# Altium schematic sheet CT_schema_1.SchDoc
size 617 x 451 mm
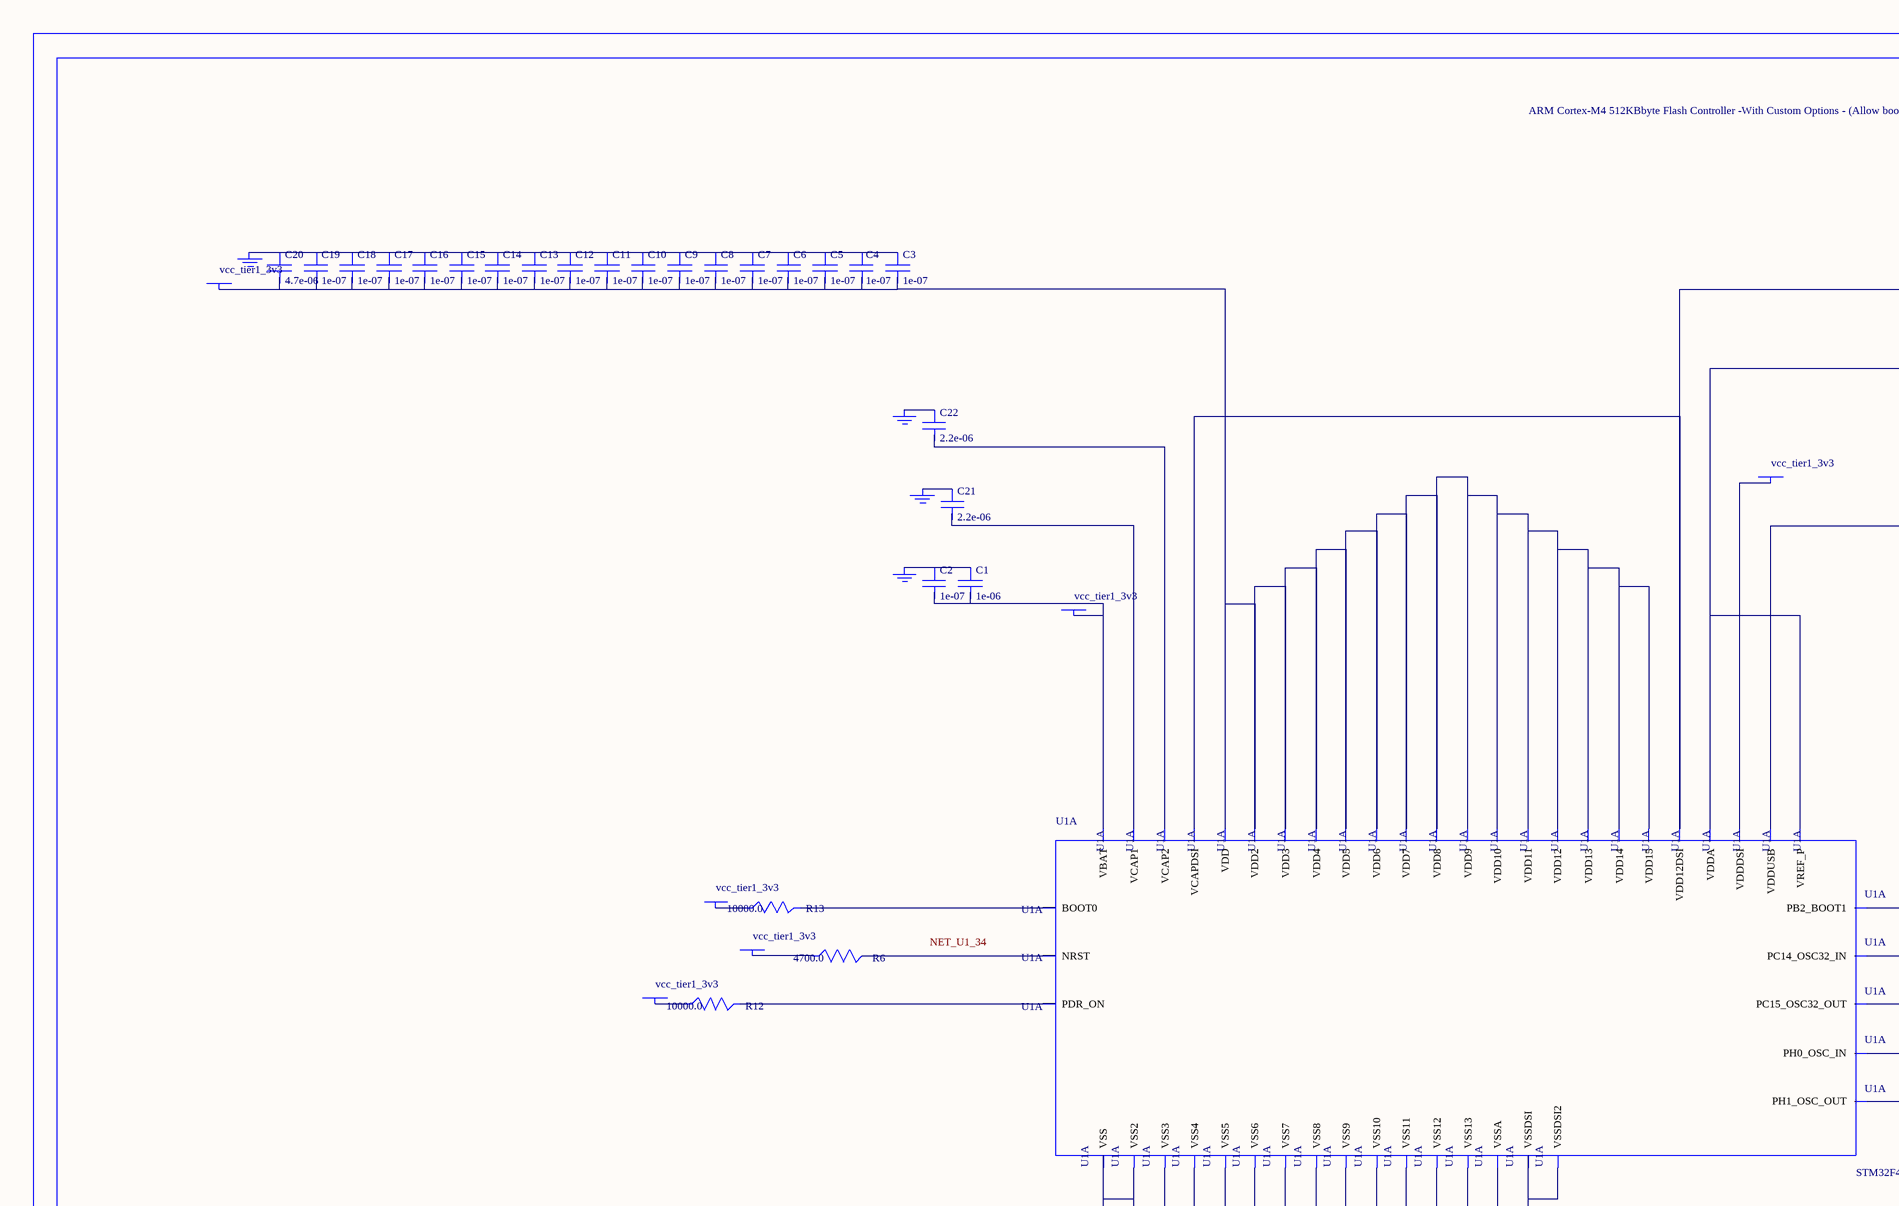
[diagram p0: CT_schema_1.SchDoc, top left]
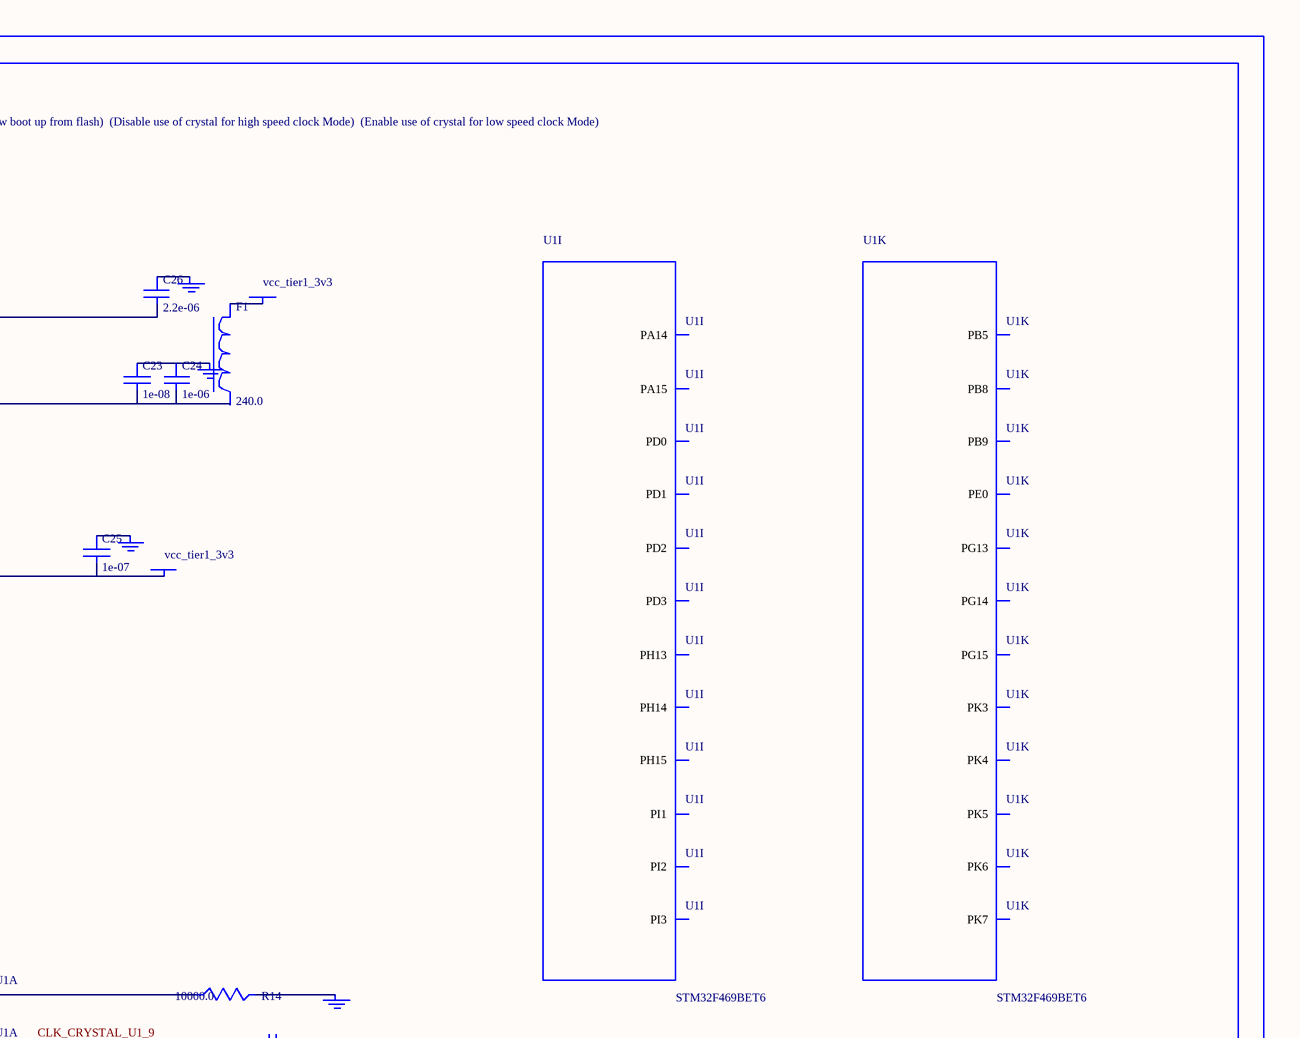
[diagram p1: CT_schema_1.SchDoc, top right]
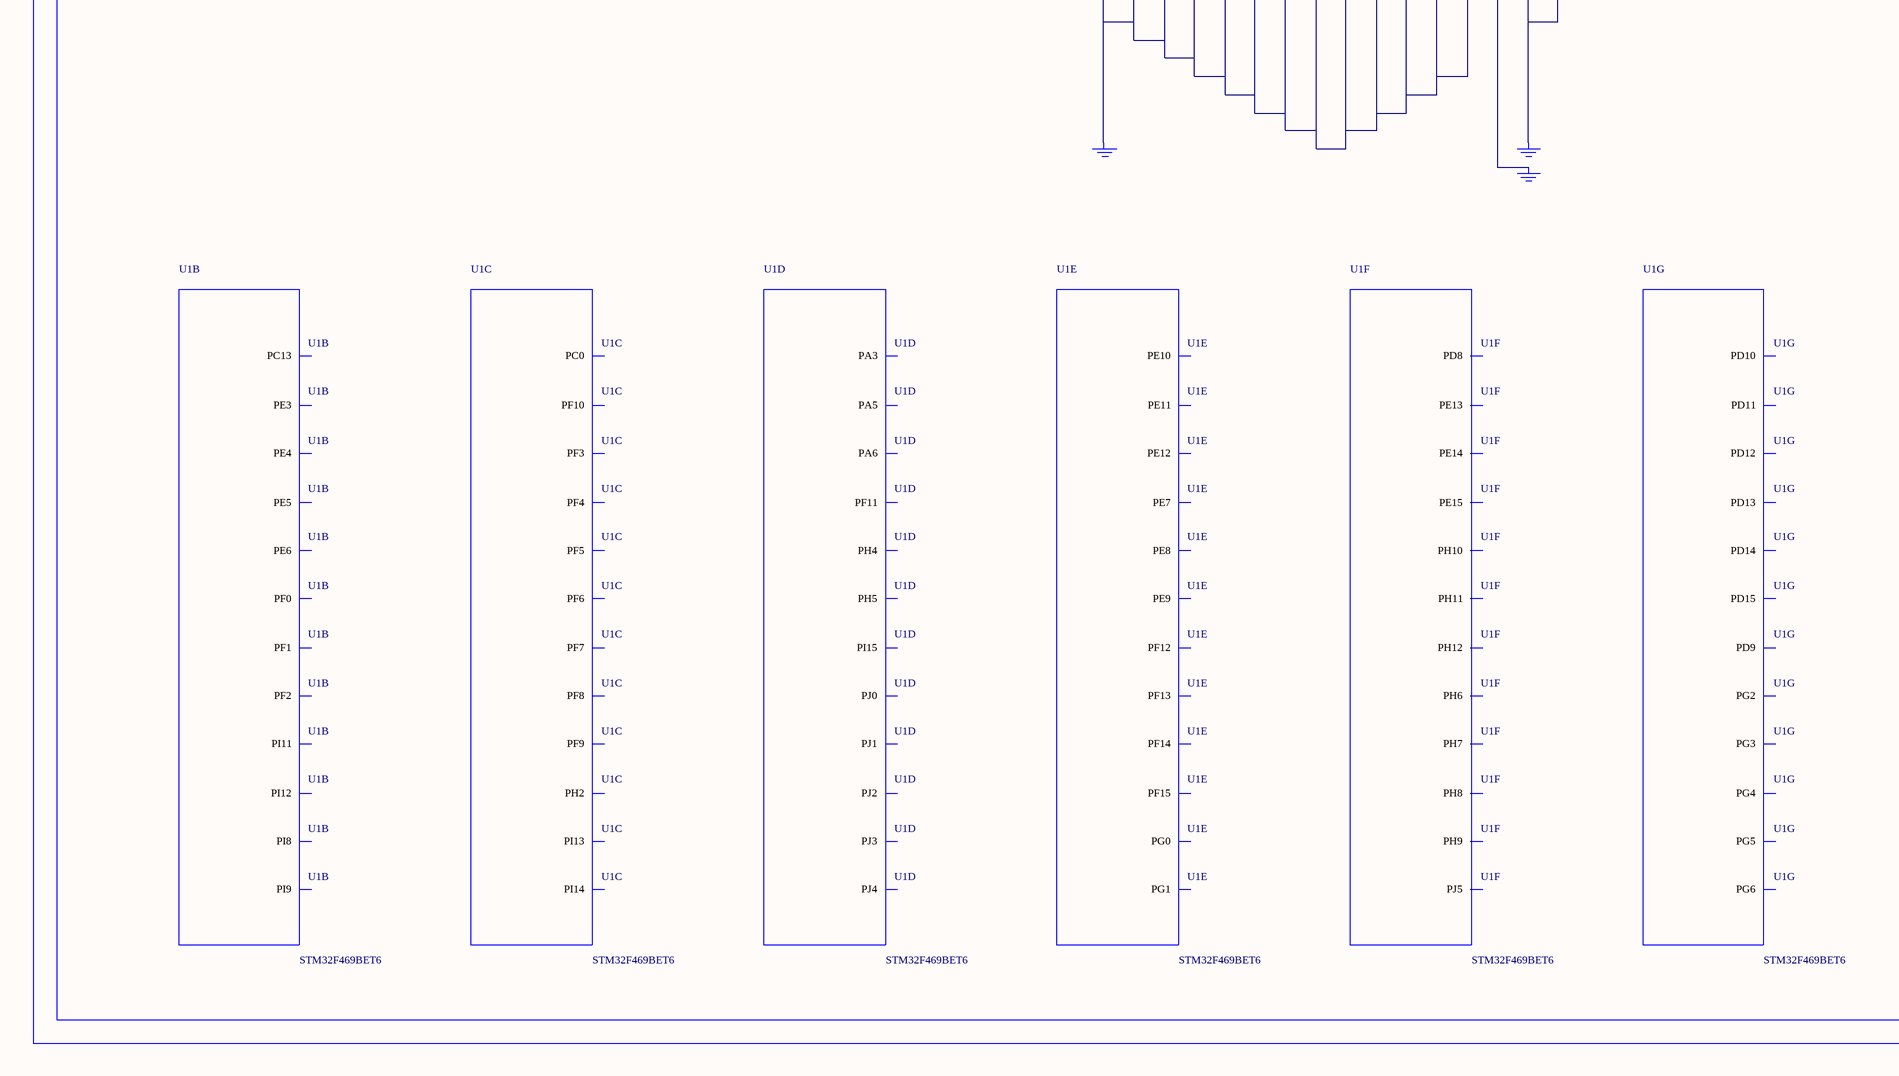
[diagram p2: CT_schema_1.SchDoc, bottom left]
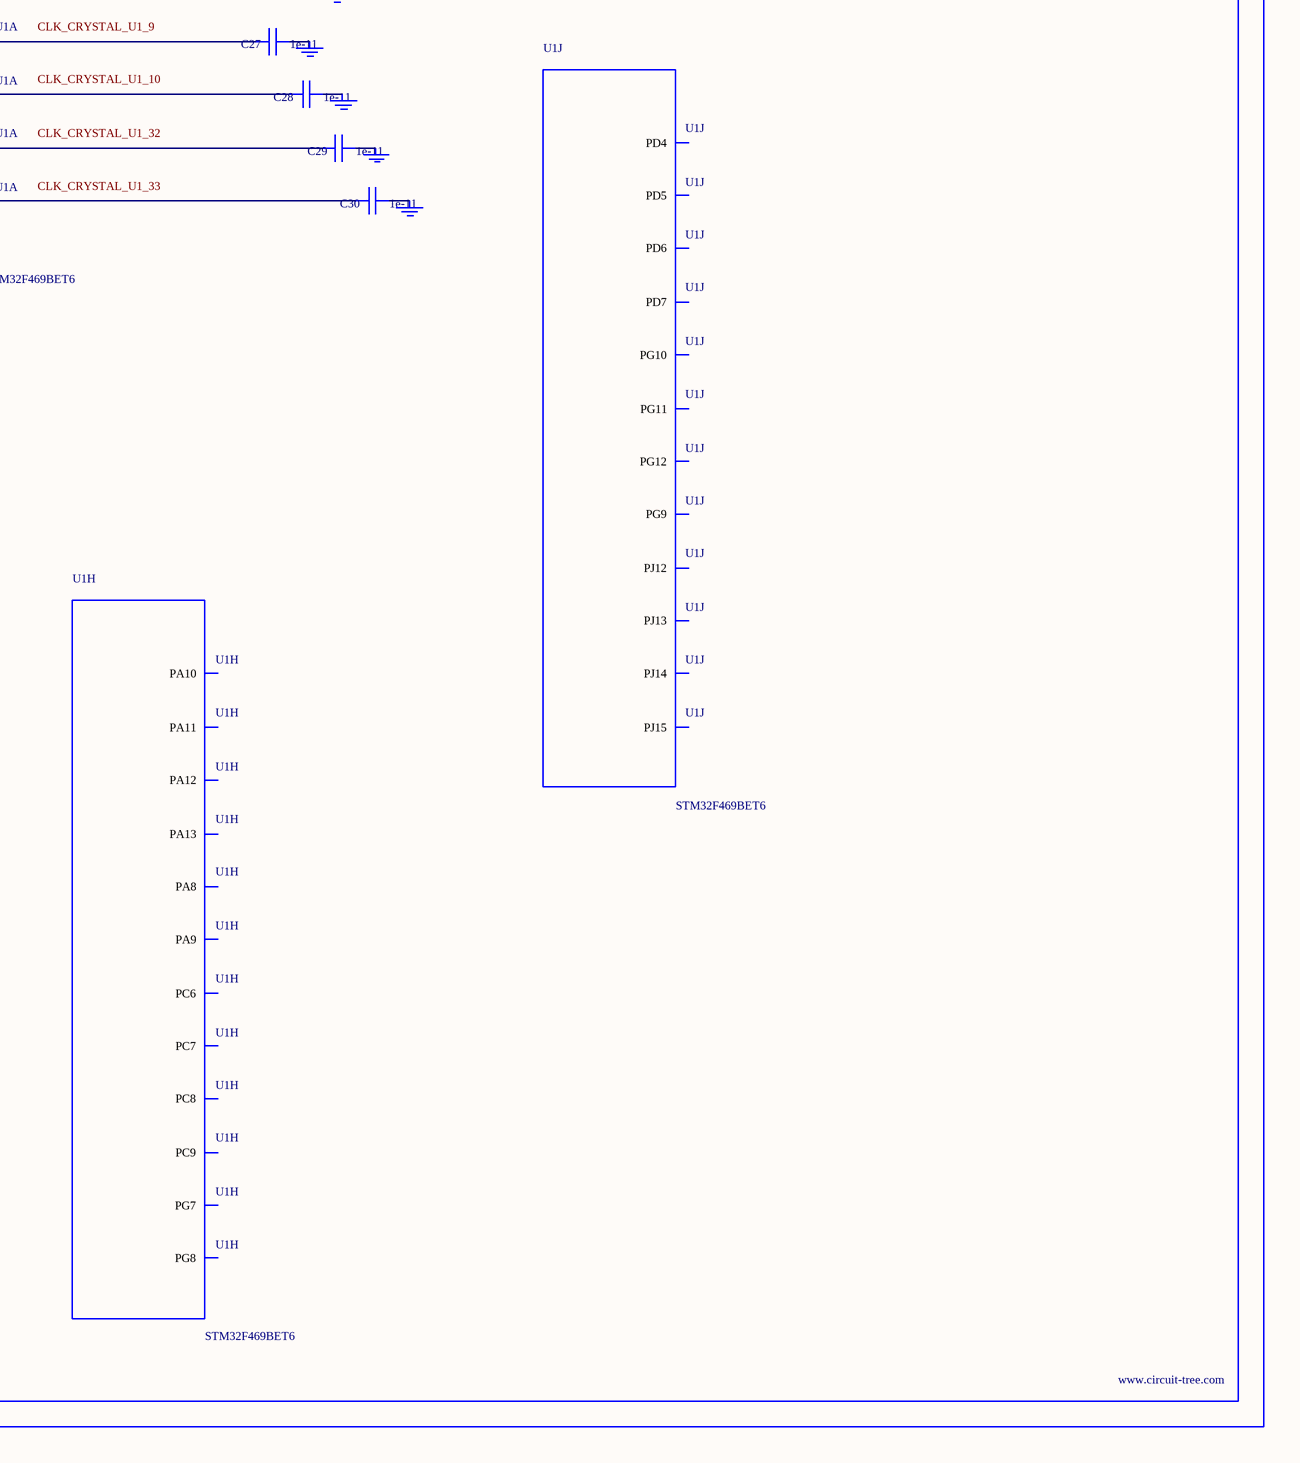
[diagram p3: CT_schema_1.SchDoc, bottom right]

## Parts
BORDER0  (no value)
C1  1e-06  [C0603]
C2  1e-07  [C0603]
C3  1e-07  [C0603]
C4  1e-07  [C0603]
C5  1e-07  [C0603]
C6  1e-07  [C0603]
C7  1e-07  [C0603]
C8  1e-07  [C0603]
C9  1e-07  [C0603]
C10  1e-07  [C0603]
C11  1e-07  [C0603]
C12  1e-07  [C0603]
C13  1e-07  [C0603]
C14  1e-07  [C0603]
C15  1e-07  [C0603]
C16  1e-07  [C0603]
C17  1e-07  [C0603]
C18  1e-07  [C0603]
C19  1e-07  [C0603]
C20  4.7e-06  [C0603]
C21  2.2e-06  [C0603]
C22  2.2e-06  [C0603]
C23  1e-08  [C0603]
C24  1e-06  [C0603]
C25  1e-07  [C0603]
C26  2.2e-06  [C0603]
C27  1e-11  [C0402]
C28  1e-11  [C0402]
C29  1e-11  [C0402]
C30  1e-11  [C0402]
F1  240.0  [L0603]
GND_INSTANCE_0_0  (no value)
GND_INSTANCE_0_1  (no value)
GND_INSTANCE_0_2  (no value)
GND_INSTANCE_0_3  (no value)
GND_INSTANCE_0_4  (no value)
GND_INSTANCE_0_5  (no value)
GND_INSTANCE_0_6  (no value)
GND_INSTANCE_0_7  (no value)
GND_INSTANCE_0_8  (no value)
GND_INSTANCE_0_9  (no value)
GND_INSTANCE_0_10  (no value)
GND_INSTANCE_0_11  (no value)
GND_INSTANCE_0_12  (no value)
GND_INSTANCE_0_13  (no value)
GND_INSTANCE_0_14  (no value)
POWER_INSTANCE_0_0  vcc_tier1_3v3
POWER_INSTANCE_0_1  vcc_tier1_3v3
POWER_INSTANCE_0_2  vcc_tier1_3v3
POWER_INSTANCE_0_3  vcc_tier1_3v3
POWER_INSTANCE_0_4  vcc_tier1_3v3
POWER_INSTANCE_0_5  vcc_tier1_3v3
POWER_INSTANCE_0_6  vcc_tier1_3v3
POWER_INSTANCE_0_7  vcc_tier1_3v3
R6  4700.0  [R0603]
R12  10000.0  [R0603]
R13  10000.0  [R0603]
R14  10000.0  [R0603]
U1  STM32F469BET6  [LQFP208]  (parts A,B,C,D,E,F,G,H,I,J,K of 18)

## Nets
NetC1_1: C1.1 C2.1 GND_INSTANCE_0_0.0(GND)
NetC1_2: C1.2 C2.2 POWER_INSTANCE_0_0.0(PWR) U1.6(VBAT)
NetC3_1: C3.1 C4.1 C5.1 C6.1 C7.1 C8.1 C9.1 C10.1 C11.1 C12.1 C13.1 C14.1 C15.1 C16.1 C17.1 C18.1 C19.1 C20.1 GND_INSTANCE_0_3.0(GND)
NetC3_2: C3.2 C4.2 C5.2 C6.2 C7.2 C8.2 C9.2 C10.2 C11.2 C12.2 C13.2 C14.2 C15.2 C16.2 C17.2 C18.2 C19.2 C20.2 POWER_INSTANCE_0_1.0(PWR) U1.15(VDD) U1.26(VDD2) U1.39(VDD3) U1.52(VDD4) U1.59(VDD5) U1.73(VDD6) U1.83(VDD7) U1.94(VDD8) U1.103(VDD9) U1.115(VDD10) U1.150(VDD11) U1.158(VDD12) U1.171(VDD13) U1.185(VDD14) U1.204(VDD15)
NetC21_1: C21.1 GND_INSTANCE_0_9.0(GND)
NetC21_2: C21.2 U1.92(VCAP1)
NetC22_1: C22.1 GND_INSTANCE_0_12.0(GND)
NetC22_2: C22.2 U1.148(VCAP2)
NetC23_1: C23.1 C24.1 GND_INSTANCE_0_7.0(GND)
NetC23_2: C23.2 C24.2 U1.41(VREF_P) U1.42(VDDA)
NetC25_1: C25.1 GND_INSTANCE_0_11.0(GND)
NetC25_2: C25.2 POWER_INSTANCE_0_4.0(PWR) U1.137(VDDUSB)
NetC26_1: C26.1 GND_INSTANCE_0_10.0(GND)
NetC26_2: C26.2 U1.119(VCAPDSI) U1.125(VDD12DSI)
NetC27_1: C27.1 GND_INSTANCE_0_1.0(GND)
NetC27_2: C27.2 U1.9(PC14_OSC32_IN)
NetC28_1: C28.1 GND_INSTANCE_0_2.0(GND)
NetC28_2: C28.2 U1.10(PC15_OSC32_OUT)
NetC29_1: C29.1 GND_INSTANCE_0_4.0(GND)
NetC29_2: C29.2 U1.32(PH0_OSC_IN)
NetC30_1: C30.1 GND_INSTANCE_0_5.0(GND)
NetC30_2: C30.2 U1.33(PH1_OSC_OUT)
NetF1_1: F1.1 POWER_INSTANCE_0_2.0(PWR)
NetGND_INSTANCE_0_6_0: GND_INSTANCE_0_6.0(GND) U1.40(VSSA)
NetGND_INSTANCE_0_8_0: GND_INSTANCE_0_8.0(GND) R14.2
NetGND_INSTANCE_0_13_0: GND_INSTANCE_0_13.0(GND) U1.14(VSS) U1.25(VSS2) U1.51(VSS3) U1.60(VSS4) U1.72(VSS5) U1.82(VSS6) U1.93(VSS7) U1.114(VSS8) U1.136(VSS9) U1.149(VSS10) U1.170(VSS11) U1.184(VSS12) U1.202(VSS13)
NetGND_INSTANCE_0_14_0: GND_INSTANCE_0_14.0(GND) U1.122(VSSDSI) U1.128(VSSDSI2)
NetPOWER_INSTANCE_0_3_0: POWER_INSTANCE_0_3.0(PWR) U1.118(VDDDSI)
NetPOWER_INSTANCE_0_5_0: POWER_INSTANCE_0_5.0(PWR) R13.1
NetPOWER_INSTANCE_0_6_0: POWER_INSTANCE_0_6.0(PWR) R12.1
NetPOWER_INSTANCE_0_7_0: POWER_INSTANCE_0_7.0(PWR) R6.1
NetR6_2: R6.2 U1.34(NRST)
NetR12_2: R12.2 U1.203(PDR_ON)
NetR13_2: R13.2 U1.197(BOOT0)
NetR14_1: R14.1 U1.63(PB2_BOOT1)

Not connected (* = marked no-connect by the designer): F1 2; U1 2(PE3) 3(PE4) 4(PE5) 5(PE6) 7(PI8) 8(PC13) 11(PI9) 13(PI11) 16(PF0) 17(PF1) 18(PF2) 19(PI12) 20(PI13) 21(PI14) 22(PF3) 23(PF4) 24(PF5) 27(PF6) 28(PF7) 29(PF8) 30(PF9) 31(PF10) 35(PC0) 46(PH2) 48(PH4) 49(PH5) 50(PA3) 54(PA5) 55(PA6) 64(PI15) 65(PJ0) 66(PJ1) 67(PJ2) 68(PJ3) 69(PJ4) 70(PF11) 71(PF12) 74(PF13) 75(PF14) 76(PF15) 77(PG0) 78(PG1) 79(PE7) 80(PE8) 81(PE9) 84(PE10) 85(PE11) 86(PE12) 87(PE13) 88(PE14) 89(PE15) 95(PJ5) 96(PH6) 97(PH7) 98(PH8) 99(PH9) 100(PH10) 101(PH11) 102(PH12) 108(PD8) 109(PD9) 110(PD10) 111(PD11) 112(PD12) 113(PD13) 116(PD14) 117(PD15) 129(PG2) 130(PG3) 131(PG4) 132(PG5) 133(PG6) 134(PG7) 135(PG8) 138(PC6) 139(PC7) 140(PC8) 141(PC9) 142(PA8) 143(PA9) 144(PA10) 145(PA11) 146(PA12) 147(PA13) 151(PH13) 152(PH14) 153(PH15) 155(PI1) 156(PI2) 157(PI3) 159(PA14) 160(PA15) 164(PD0) 165(PD1) 166(PD2) 167(PD3) 168(PD4) 169(PD5) 172(PD6) 173(PD7) 174(PJ12) 175(PJ13) 176(PJ14) 177(PJ15) 178(PG9) 179(PG10) 180(PG11) 181(PG12) 182(PG13) 183(PG14) 186(PK3) 187(PK4) 188(PK5) 189(PK6) 190(PK7) 191(PG15) 194(PB5) 198(PB8) 199(PB9) 200(PE0)

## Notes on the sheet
- Labels drawn without touching a wire or pin: CLK_CRYSTAL_U1_9, CLK_CRYSTAL_U1_10, CLK_CRYSTAL_U1_32, CLK_CRYSTAL_U1_33, NET_U1_34

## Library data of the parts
BORDER0 = BORDER_PAGE0
C1 C24 = C0603C105K3RACTU
C2-C19 C25 = 06035C104K4Z2A
C20 = GRM188R6YA475KE15D
C21 C22 C26 = C0603C225K8RACTU
C23 = 06035C103K4Z2A
C27-C30 = C0402C100K3GACTU
F1 = Z0603C241ASMST
GND_INSTANCE_0_0-GND_INSTANCE_0_14 = GND
POWER_INSTANCE_0_0-POWER_INSTANCE_0_7 = PWR
R6 = RC0603JR-074K7L
R12-R14 = RC0603JR-0710KL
